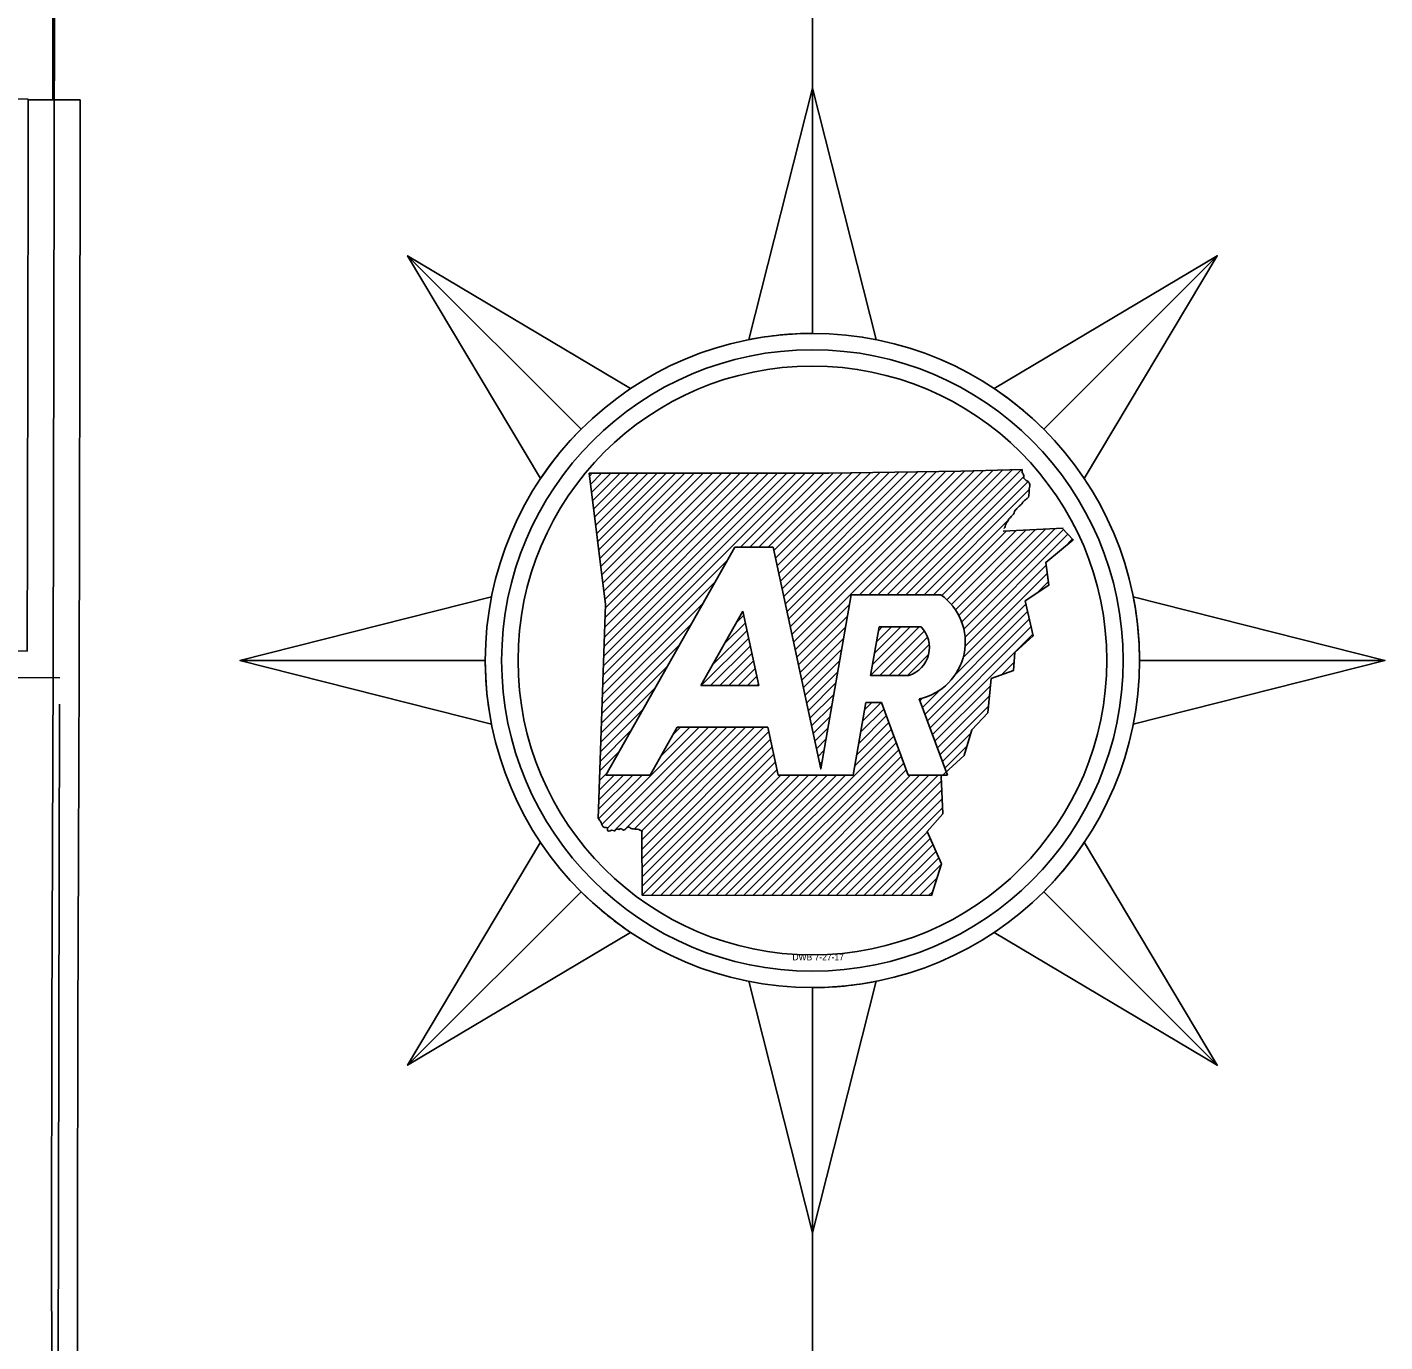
# Model space of a CAD drawing. Extents: x -4306 to 3843, y 131 to 8053.
# Drawn here: x 2258 to 2886, y 2832 to 3441 of the extents above; entities that cross this region are included whole.
import ezdxf

# ---------------------------------------------------------------- set-up
doc = ezdxf.new("R2010")
doc.units = 0
for name, color, linetype in [('32', 7, 'Continuous'), ('34', 7, 'Continuous'), ('6', 7, 'Continuous'), ('R_No Plot', 7, 'Continuous')]:
    doc.layers.add(name, color=color, linetype=linetype)

msp = doc.modelspace()

# ---------------------------------------------------------------- linework, layer by layer
at = {"layer": '32'}
for p, q in [((2270.85, 3567.21), (2270.04, 3142.68)), ((2270.85, 3567.21), (2270.04, 3142.68)), ((2258.54, 3407.32), (2258.48, 3377.43)), ((2258.54, 3407.08), (2282.54, 3407.04)), ((2282.54, 3407.04), (2282.49, 3377.39)), ((2258.48, 3377.43), (2258.32, 3292.94)), ((2282.49, 3377.39), (2282.32, 3292.9)), ((2258.32, 3292.94), (2258.16, 3208.46)), ((2282.32, 3292.9), (2282.16, 3208.41)), ((2258.16, 3208.46), (2258.05, 3151.99)), ((2282.16, 3208.41), (2282.04, 3142.64)), ((1434.17, 3147), (2273.16, 3139.63)), ((2258.05, 3151.99), (2192.34, 3152.57)), ((2270.04, 3142.68), (2269.48, 2980.32)), ((2270.04, 3142.68), (2269.48, 2980.32)), ((2282.04, 3142.64), (2281.75, 3058.15)), ((2270.28, 1873.49), (2272.99, 3127.43)), ((2270.28, 1873.49), (2272.99, 3127.43)), ((2281.75, 3058.15), (2281.48, 2980.28)), ((2269.48, 2980.32), (2269.29, 2874.85)), ((2269.48, 2980.32), (2269.29, 2874.85)), ((2281.48, 2980.28), (2281.47, 2973.68)), ((2281.47, 2973.68), (2281.32, 2889.19)), ((2281.32, 2889.19), (2281.29, 2874.85)), ((2269.29, 2874.85), (2269.51, 2717.26)), ((2269.29, 2874.85), (2269.51, 2717.26)), ((2281.29, 2874.85), (2281.39, 2804.74))]:
    msp.add_line(p, q, dxfattribs=at)
at = {"layer": '34'}
msp.add_line((2269.91, 3407.19), (2270.13, 3568.15), dxfattribs=at)
at = {"layer": '6'}
msp.add_line((1458.68, 3416.72), (2258.54, 3407.32), dxfattribs=at)
at = {"layer": 'R_No Plot'}
for p, q in [((2621.3, 3912.98), (2621.3, 3315.55)), ((2621.3, 3412.53), (2591.83, 3296.13)), ((2621.3, 3299.03), (2621.3, 3412.53)), ((2434.03, 3334.96), (2514.29, 3254.71)), ((2514.29, 3254.71), (2434.03, 3334.96)), ((2434.03, 3334.96), (2495.5, 3231.82)), ((2808.56, 3334.96), (2705.42, 3273.49)), ((2728.3, 3254.71), (2808.56, 3334.96)), ((2728.3, 3254.71), (2808.56, 3334.96)), ((2605.78, 3187.94), (2652.61, 3234.77)), ((2606.54, 3184.42), (2656.96, 3234.84)), ((2607.29, 3180.89), (2661.31, 3234.9)), ((2608.05, 3177.36), (2665.65, 3234.97)), ((2608.8, 3173.84), (2670, 3235.04)), ((2609.56, 3170.31), (2674.35, 3235.11)), ((2610.31, 3166.79), (2678.7, 3235.17)), ((2611.06, 3163.26), (2683.05, 3235.24)), ((2611.82, 3159.74), (2687.39, 3235.31)), ((2612.57, 3156.21), (2691.75, 3235.39)), ((2613.33, 3152.68), (2696.14, 3235.49)), ((2643.06, 3178.14), (2700.52, 3235.59)), ((2647.34, 3178.14), (2704.9, 3235.7)), ((2651.62, 3178.14), (2709.28, 3235.8)), ((2655.9, 3178.14), (2713.66, 3235.9)), ((2660.18, 3178.14), (2718.05, 3236)), ((2518.14, 3232.99), (2519.48, 3234.33)), ((2518.62, 3229.19), (2523.76, 3234.32)), ((2519.09, 3225.38), (2528.03, 3234.32)), ((2519.57, 3221.57), (2532.31, 3234.32)), ((2520.04, 3217.77), (2536.59, 3234.32)), ((2520.52, 3213.96), (2540.87, 3234.31)), ((2520.99, 3210.15), (2545.15, 3234.31)), ((2521.46, 3206.35), (2549.42, 3234.31)), ((2521.94, 3202.54), (2553.7, 3234.3)), ((2522.41, 3198.74), (2557.98, 3234.3)), ((2522.89, 3194.93), (2562.26, 3234.3)), ((2523.36, 3191.12), (2566.53, 3234.3)), ((2523.83, 3187.32), (2570.81, 3234.29)), ((2524.31, 3183.51), (2575.09, 3234.29)), ((2524.45, 3140.85), (2617.98, 3234.38)), ((2524.6, 3145.28), (2613.69, 3234.37)), ((2524.74, 3149.71), (2609.4, 3234.36)), ((2524.78, 3179.7), (2579.37, 3234.3)), ((2524.89, 3154.13), (2605.11, 3234.35)), ((2525.04, 3158.56), (2600.82, 3234.34)), ((2525.18, 3162.99), (2596.53, 3234.33)), ((2525.26, 3175.9), (2583.66, 3234.3)), ((2525.33, 3167.41), (2592.24, 3234.32)), ((2525.48, 3171.84), (2587.95, 3234.31)), ((2588.01, 3200.13), (2622.27, 3234.39)), ((2592.29, 3200.13), (2626.56, 3234.4)), ((2596.57, 3200.13), (2630.87, 3234.43)), ((2600.85, 3200.13), (2635.22, 3234.5)), ((2603.52, 3198.52), (2639.57, 3234.57)), ((2604.27, 3194.99), (2643.92, 3234.63)), ((2605.03, 3191.47), (2648.26, 3234.7)), ((2664.46, 3178.14), (2719, 3232.67)), ((2668.74, 3178.14), (2721.07, 3230.46)), ((2673.02, 3178.14), (2721.62, 3226.74)), ((2677.3, 3178.14), (2711.85, 3212.68)), ((2681.19, 3177.75), (2711.01, 3207.56)), ((2683.53, 3175.8), (2715.52, 3207.79)), ((2685.62, 3173.61), (2720.03, 3208.02)), ((2687.47, 3171.18), (2724.54, 3208.26)), ((2689.06, 3168.49), (2729.06, 3208.49)), ((2690.36, 3165.52), (2733.57, 3208.72)), ((2691.35, 3162.22), (2737.63, 3208.5)), ((2691.93, 3158.52), (2739.63, 3206.22)), ((2737.73, 3200.04), (2741.63, 3203.94)), ((2525.72, 3094.69), (2585.43, 3200.13)), ((2585.43, 3200.13), (2603.17, 3200.13)), ((2524.3, 3136.42), (2582.06, 3194.18)), ((2691.95, 3154.26), (2729.42, 3191.73)), ((2691.06, 3149.09), (2729.91, 3187.94)), ((2524.16, 3132), (2576.47, 3184.31)), ((2725.11, 3178.86), (2730.4, 3184.15)), ((2524.01, 3127.57), (2570.89, 3174.44)), ((2614.08, 3149.16), (2638.37, 3173.45)), ((2639.19, 3178.14), (2680.65, 3178.14)), ((2687.34, 3141.09), (2720.04, 3173.79)), ((2886.12, 3147.7), (2769.73, 3177.17)), ((2569.65, 3136.07), (2589.17, 3170.56)), ((2586.14, 3165.2), (2589.58, 3168.65)), ((2614.84, 3145.63), (2637.47, 3168.26)), ((2673.39, 3122.86), (2720.84, 3170.31)), ((2674.54, 3119.73), (2721.64, 3166.83)), ((2523.86, 3123.14), (2565.3, 3164.58)), ((2574.96, 3145.47), (2591.09, 3161.6)), ((2580.55, 3155.33), (2590.34, 3165.12)), ((2615.59, 3142.11), (2636.56, 3163.08)), ((2648.21, 3140.74), (2670.73, 3163.25)), ((2649.09, 3145.89), (2666.45, 3163.25)), ((2649.99, 3151.07), (2662.17, 3163.25)), ((2650.89, 3156.26), (2657.89, 3163.25)), ((2651.8, 3161.44), (2653.61, 3163.25)), ((2652.11, 3163.25), (2671.58, 3163.25)), ((2652.49, 3140.74), (2673.11, 3161.35)), ((2675.7, 3116.61), (2722.44, 3163.35)), ((2676.85, 3113.48), (2723.24, 3159.87)), ((2523.72, 3118.72), (2559.71, 3154.71)), ((2569.85, 3136.07), (2591.85, 3158.07)), ((2574.13, 3136.07), (2592.6, 3154.55)), ((2616.35, 3138.58), (2635.66, 3157.89)), ((2656.77, 3140.74), (2674.55, 3158.52)), ((2661.05, 3140.74), (2675.35, 3155.03)), ((2356.47, 3147.7), (2469.97, 3147.7)), ((2469.97, 3147.7), (2356.47, 3147.7)), ((2356.47, 3147.7), (2472.86, 3118.23)), ((2578.41, 3136.07), (2593.36, 3151.02)), ((2582.69, 3136.07), (2594.11, 3147.49)), ((2617.1, 3135.05), (2634.76, 3152.71)), ((2617.86, 3131.53), (2633.85, 3147.53)), ((2665.33, 3140.74), (2674.99, 3150.39)), ((2708.61, 3140.96), (2714.61, 3146.96)), ((2772.63, 3147.7), (2886.12, 3147.7)), ((2772.63, 3147.7), (2886.12, 3147.7)), ((2523.57, 3114.29), (2554.12, 3144.84)), ((2586.97, 3136.07), (2594.87, 3143.97)), ((2618.61, 3128), (2632.95, 3142.34)), ((2648.19, 3140.74), (2665.97, 3140.74)), ((2523.42, 3109.86), (2548.53, 3134.97)), ((2569.65, 3136.07), (2596.56, 3136.07)), ((2591.25, 3136.07), (2595.62, 3140.44)), ((2595.53, 3136.07), (2596.38, 3136.92)), ((2619.36, 3124.48), (2632.05, 3137.16)), ((2678.01, 3110.36), (2703.68, 3136.03)), ((2620.12, 3120.95), (2631.14, 3131.98)), ((2644.52, 3119.67), (2653.07, 3128.22)), ((2645.42, 3124.85), (2648.79, 3128.22)), ((2653.19, 3128.22), (2646.01, 3128.22)), ((2665.58, 3094.69), (2653.19, 3128.22)), ((2670.74, 3130.01), (2683.8, 3094.69)), ((2671.08, 3129.11), (2672.38, 3130.41)), ((2672.23, 3125.98), (2680.38, 3134.13)), ((2679.16, 3107.23), (2703.2, 3131.27)), ((2523.28, 3105.43), (2542.95, 3125.11)), ((2620.87, 3117.43), (2630.24, 3126.79)), ((2642.71, 3109.3), (2655.47, 3122.06)), ((2643.61, 3114.48), (2654.31, 3125.19)), ((2680.32, 3104.1), (2702.72, 3126.51)), ((2523.91, 3071.83), (2568.9, 3116.81)), ((2526.45, 3070.09), (2573.18, 3116.81)), ((2529.53, 3068.88), (2577.46, 3116.81)), ((2534.61, 3069.69), (2581.74, 3116.81)), ((2538.96, 3069.75), (2586.02, 3116.81)), ((2542.31, 3068.83), (2590.3, 3116.81)), ((2542.46, 3064.69), (2594.58, 3116.81)), ((2542.47, 3060.42), (2598.86, 3116.81)), ((2558.74, 3116.81), (2546.21, 3094.69)), ((2551.06, 3103.26), (2564.62, 3116.81)), ((2556.65, 3113.13), (2560.34, 3116.81)), ((2600.68, 3116.81), (2558.74, 3116.81)), ((2621.63, 3113.9), (2629.34, 3121.61)), ((2622.38, 3110.37), (2628.43, 3116.43)), ((2640.9, 3098.93), (2657.78, 3115.81)), ((2641.81, 3104.12), (2656.62, 3118.93)), ((2523.13, 3101.01), (2537.36, 3115.24)), ((2542.48, 3056.15), (2601.11, 3114.79)), ((2542.49, 3051.88), (2601.87, 3111.26)), ((2585.31, 3039.06), (2658.93, 3112.68)), ((2589.59, 3039.06), (2660.09, 3109.56)), ((2623.14, 3106.85), (2627.53, 3111.24)), ((2681.47, 3100.98), (2694.6, 3114.1)), ((2522.98, 3096.58), (2531.77, 3105.37)), ((2542.5, 3047.61), (2602.62, 3107.73)), ((2542.51, 3043.34), (2603.37, 3104.21)), ((2593.86, 3039.05), (2661.24, 3106.43)), ((2598.13, 3039.04), (2662.4, 3103.31)), ((2623.89, 3103.32), (2626.63, 3106.06)), ((2682.63, 3097.85), (2692.76, 3107.99)), ((2542.58, 3039.13), (2604.13, 3100.68)), ((2546.85, 3039.13), (2604.88, 3097.16)), ((2602.41, 3039.04), (2663.55, 3100.18)), ((2606.68, 3039.03), (2664.71, 3097.06)), ((2624.65, 3099.8), (2625.72, 3100.87)), ((2522.31, 3074.51), (2542.49, 3094.69)), ((2522.39, 3078.87), (2538.21, 3094.69)), ((2522.54, 3083.3), (2533.93, 3094.69)), ((2522.69, 3087.73), (2529.65, 3094.69)), ((2522.84, 3092.15), (2526.18, 3095.5)), ((2546.21, 3094.69), (2525.72, 3094.69)), ((2551.13, 3039.12), (2606.69, 3094.69)), ((2555.4, 3039.11), (2610.97, 3094.69)), ((2559.67, 3039.11), (2615.25, 3094.69)), ((2563.95, 3039.1), (2619.53, 3094.69)), ((2568.22, 3039.09), (2623.81, 3094.69)), ((2572.49, 3039.09), (2628.1, 3094.69)), ((2576.77, 3039.08), (2632.38, 3094.69)), ((2581.04, 3039.07), (2636.66, 3094.69)), ((2640.16, 3094.69), (2605.41, 3094.69)), ((2610.95, 3039.02), (2666.62, 3094.69)), ((2615.23, 3039.02), (2670.9, 3094.69)), ((2619.5, 3039.01), (2675.18, 3094.69)), ((2623.77, 3039), (2679.46, 3094.69)), ((2628.05, 3038.99), (2680.89, 3091.84)), ((2683.8, 3094.69), (2665.58, 3094.69)), ((2632.32, 3038.99), (2681.08, 3087.75)), ((2636.59, 3038.98), (2681.27, 3083.66)), ((2640.87, 3038.97), (2681.47, 3079.57)), ((2645.14, 3038.97), (2674.44, 3068.26)), ((2649.41, 3038.96), (2675.76, 3065.3)), ((2653.69, 3038.95), (2677.08, 3062.34)), ((2657.96, 3038.95), (2678.4, 3059.39)), ((2808.56, 2960.44), (2747.09, 3063.58)), ((2662.23, 3038.94), (2679.72, 3056.43)), ((2666.51, 3038.93), (2680.83, 3053.25)), ((2670.78, 3038.92), (2678.89, 3047.03)), ((2434.03, 2960.44), (2514.29, 3040.69)), ((2514.29, 3040.69), (2434.03, 2960.44)), ((2675.05, 3038.92), (2676.95, 3040.82)), ((2728.3, 3040.69), (2808.56, 2960.44)), ((2728.3, 3040.69), (2808.56, 2960.44)), ((2434.03, 2960.44), (2537.18, 3021.9)), ((2621.29, 2996.37), (2621.3, 2996.38)), ((2621.3, 2882.87), (2650.76, 2999.27)), ((2621.3, 2996.37), (2621.3, 2511.93)), ((2621.3, 2996.37), (2621.3, 2882.87))]:
    msp.add_line(p, q, dxfattribs=at)
for points in [[(2591.83, 3296.13), (2621.3, 3412.53), (2650.76, 3296.13)], [(2495.5, 3231.82), (2434.03, 3334.96), (2537.18, 3273.49)], [(2705.42, 3273.49), (2808.56, 3334.96), (2747.09, 3231.82)], [(2517.98, 3234.33), (2577.03, 3234.29), (2628.85, 3234.4), (2689.98, 3235.35), (2718.32, 3236.01)], [(2522.25, 3074.56), (2525.54, 3173.63), (2517.98, 3234.33)], [(2736.87, 3208.87), (2741.98, 3203.54), (2729.24, 3193.07), (2730.62, 3182.49), (2719.69, 3175.29), (2723.43, 3159.03), (2715.01, 3151.35), (2714.26, 3142.99), (2704.01, 3139.31), (2702.42, 3123.55), (2695.06, 3115.67), (2691.51, 3103.8), (2680.79, 3093.99), (2681.6, 3076.68), (2674.32, 3068.52), (2680.96, 3053.67), (2676.36, 3038.92)], [(2709.56, 3207.49), (2737.27, 3208.91)], [(2603.17, 3200.13), (2625.14, 3097.51), (2639.19, 3178.14)], [(2472.86, 3118.23), (2356.47, 3147.7), (2472.86, 3177.17)], [(2769.73, 3177.17), (2886.12, 3147.7), (2769.73, 3118.23)], [(2589.17, 3170.56), (2596.56, 3136.07)], [(2648.19, 3140.74), (2652.11, 3163.25)], [(2646.01, 3128.22), (2640.16, 3094.69)], [(2605.41, 3094.69), (2600.68, 3116.81)], [(2676.36, 3038.92), (2542.52, 3039.13), (2542.45, 3068.68)], [(2537.18, 3021.9), (2434.03, 2960.44), (2495.5, 3063.58)], [(2747.09, 3063.58), (2808.56, 2960.44), (2705.42, 3021.9)], [(2650.76, 2999.27), (2621.3, 2882.87), (2591.83, 2999.27)]]:
    msp.add_lwpolyline(points, dxfattribs=at)
for radius in [151.33, 143.76, 136.2]:
    msp.add_circle((2621.3, 3147.7), radius, dxfattribs=at)
for centre, radius, start, end in [((2621.3, 3147.7), 151.33, 90, 101.22909), ((2621.3, 3147.7), 151.33, 45, 56.22909), ((2621.3, 3147.7), 151.33, 135, 146.22909), ((2665.24, 3156.23), 26.79, 281.86262, 54.87052), ((2621.3, 3147.7), 151.33, 0, 11.22909), ((2661.71, 3153.76), 13.7, 288.12683, 43.89016), ((2621.3, 3147.7), 151.33, 180, 191.22909), ((2621.3, 3147.7), 151.33, 315, 326.22909), ((2621.3, 3147.7), 151.33, 225, 236.22909), ((2621.3, 3147.7), 151.33, 270, 281.22909)]:
    msp.add_arc(centre, radius, start, end, dxfattribs=at)
for points in [[(2718.32, 3236.01), (2718.5, 3234.4), (2719.01, 3233.56), (2719.09, 3232.03), (2719.71, 3231.37), (2720.77, 3230.71), (2721.72, 3229.65), (2721.94, 3228.41), (2721.64, 3227.13), (2721.57, 3225.71), (2721.42, 3224.47), (2721.21, 3223.33), (2720.33, 3222.42), (2719.49, 3221.76), (2718.72, 3221), (2718.17, 3220.19), (2717.22, 3219.32), (2716.28, 3218.4), (2715.51, 3217.6), (2714.74, 3216.58), (2714.38, 3215.45), (2713.54, 3214.64), (2712.88, 3213.91), (2712, 3212.93), (2711.56, 3211.94), (2710.72, 3210.81), (2710.54, 3209.71), (2709.99, 3208.84), (2709.96, 3208.69)], [(2542.45, 3068.68), (2542.59, 3068.6), (2541.9, 3069.08), (2540.95, 3069.55), (2539.89, 3069.63), (2538.54, 3069.81), (2537.41, 3069.92), (2536.24, 3070.69), (2535, 3069.88), (2533.61, 3069.3), (2532.81, 3069.96), (2531.75, 3069.52), (2531.02, 3069.74), (2529.74, 3068.86), (2528.53, 3069.19), (2527.66, 3068.93), (2526.56, 3068.97), (2526.34, 3070.21), (2525.28, 3070.39), (2524.37, 3070.91), (2523.75, 3072.18), (2523.31, 3073.17), (2522.25, 3074.56)]]:
    msp.add_spline(points, degree=3, dxfattribs=at)

# ---------------------------------------------------------------- texts
msp.add_text('DWB 7-27-17', height=2.9425, dxfattribs=at).set_placement((2612.03, 3008.98))

doc.saveas('drawing.dxf')
